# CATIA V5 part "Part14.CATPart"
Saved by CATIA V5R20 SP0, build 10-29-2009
Part number: bielle_1_hab
Bounding box of the stored display mesh (mm): x 0 to 0.05, y -0.1 to 2.17, z -0.1 to 2.27
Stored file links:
  D:\Dropbox\IAO_2012\IAO_2012_718_ccascaro\ccascaro\Part14.CATPart
  C:\Users\Cédric\Documents\IFMA-2A\IAO\Projet IAO\Projet IAO catia\ass_bielles_skl.CATProduct
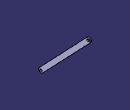
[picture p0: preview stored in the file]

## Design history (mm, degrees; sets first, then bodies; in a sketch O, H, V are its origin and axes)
Set1
  Point1 "point A": linked copy from another document
  Point2 "point B": linked copy from another document
Body1 (main body)
  Sketch1 on yz-plane, origin (0, 0, 0), H (0, 1, 0), V (0, 0, 1)
    construction line L1 (0, 0) -> (2.07, 2.17)
    point P1 (0, 0)
    point P2 (2.07, 2.17)
    line L2 (-0.0724, 0.069) -> (1.9976, 2.239)
    line L3 (2.1424, 2.101) -> (0.0724, -0.069)
    arc A1 centre (2.07, 2.17) radius 0.1 from (1.9976, 2.239) to (2.1424, 2.101) cw
    arc A2 centre (0, 0) radius 0.1 from (0.0724, -0.069) to (-0.0724, 0.069) cw
    reference projected point E1 (2.07, 2.17) from Point2
    reference projected point E2 (0, 0) from Point1
    circle A3 centre (2.07, 2.17) radius 0.05
    circle A4 centre (0, 0) radius 0.05
    distance L1 L2 = 0.1
    distance P2 E1 = 0
    distance P1 E2 = 0
    tangency: A1 L2, A2 L2, A1 L3, A2 L3
  Pad1: profile Sketch1, direction (1, 0, 0), length 0.05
